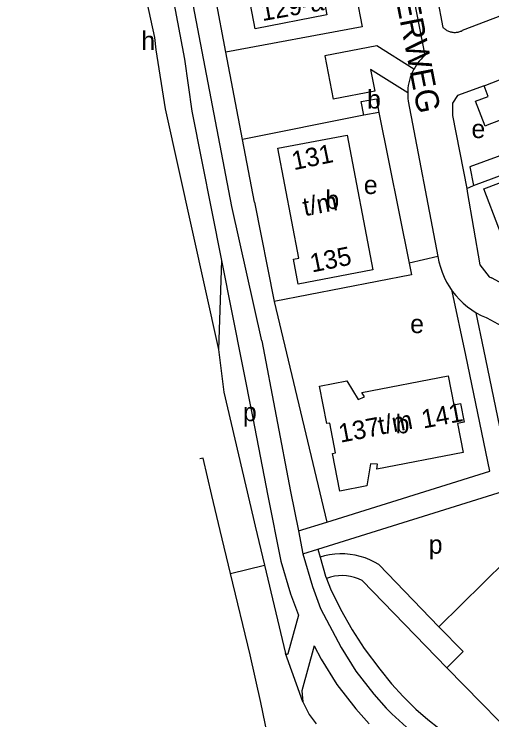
# Model space of a CAD drawing. Extents: x 159261 to 160849, y 382514 to 384534.
# Drawn here: x 159284.6 to 159387.5, y 383631.8 to 383783.7 of the extents above; entities that cross this region are included whole.
import ezdxf

# ---------------------------------------------------------------- set-up
doc = ezdxf.new("R2010")
doc.units = 0
for name, color, linetype in [('BLT_Basislijn', 7, 'Continuous'), ('BLT_Bebouwing', 7, 'Continuous'), ('BLT_Centroide', 7, 'Continuous'), ('BLT_Huisnummer_reeks', 7, 'Continuous'), ('BLT_Straatnaam', 7, 'Continuous'), ('BLT_Vlakafsluiter', 7, 'Continuous')]:
    doc.layers.add(name, color=color, linetype=linetype)

msp = doc.modelspace()

# ---------------------------------------------------------------- linework, layer by layer
at = {"layer": 'BLT_Basislijn'}
for p, q in [((159331.48, 383742.29), (159313.79, 383834.72)), ((159363.49, 383824.34), (159372.99, 383774.82)), ((159330.21, 383775.53), (159323.42, 383811.02)), ((159372.94, 383801.64), (159376.92, 383780.88)), ((159357.47, 383791.8), (159359.52, 383781.02)), ((159359.52, 383781.02), (159330.21, 383775.53)), ((159333.81, 383756.74), (159330.21, 383775.53)), ((159362.71, 383776.89), (159351.53, 383774.75)), ((159370.65, 383771.88), (159362.71, 383776.89)), ((159351.53, 383774.75), (159353.31, 383765.45)), ((159361.34, 383771.84), (159362.27, 383767.17)), ((159369.33, 383766.81), (159361.34, 383771.84)), ((159362.27, 383767.17), (159353.31, 383765.45)), ((159369.45, 383765), (159375.85, 383731.55)), ((159359.9, 383761.96), (159333.81, 383756.74)), ((159363.15, 383762.56), (159369.66, 383730.13)), ((159336.39, 383743.23), (159333.81, 383756.74)), ((159382.03, 383746.18), (159383.52, 383746.85)), ((159337.91, 383713.36), (159331.48, 383742.29)), ((159336.39, 383743.23), (159340.62, 383721.83)), ((159375.85, 383731.55), (159369.66, 383730.13)), ((159340.62, 383721.83), (159351.9, 383674.35)), ((159386.34, 383718.35), (159393.73, 383714.24)), ((159349.98, 383668.51), (159405.99, 383686.02)), ((159351.9, 383674.35), (159386.99, 383685.32)), ((159345.82, 383672.45), (159351.9, 383674.35)), ((159346.8, 383667.51), (159349.98, 383668.51)), ((159376.05, 383651.84), (159363.13, 383665.21)), ((159377.74, 383643), (159359.51, 383661.77))]:
    msp.add_line(p, q, dxfattribs=at)
for points in [[(159284.62, 383935.86), (159290.4, 383905.35), (159296.75, 383872.44), (159307.34, 383816.38), (159311.89, 383792.28), (159314.82, 383778.68), (159315.15, 383776.07), (159317.1, 383763.37)], [(159301.4, 383876.04), (159302.79, 383871.79), (159313.75, 383813.92), (159321.28, 383774.05), (159322.88, 383762.86)], [(159454.25, 383808.11), (159381.04, 383780.17)], [(159376.92, 383780.88), (159377.04, 383780.76), (159377.18, 383780.64), (159377.32, 383780.53), (159377.47, 383780.42), (159377.62, 383780.32), (159377.79, 383780.23), (159377.95, 383780.15), (159378.13, 383780.07), (159378.31, 383780), (159378.49, 383779.94), (159378.68, 383779.9), (159378.87, 383779.86), (159379.06, 383779.83), (159379.25, 383779.81), (159379.44, 383779.81), (159379.63, 383779.81), (159379.82, 383779.82), (159380.01, 383779.85), (159380.19, 383779.88), (159380.37, 383779.92), (159380.55, 383779.97), (159380.72, 383780.03), (159380.88, 383780.09), (159381.04, 383780.17)], [(159372.99, 383774.82), (159372.59, 383774.44), (159372.2, 383774.04), (159371.83, 383773.61), (159371.48, 383773.16), (159371.15, 383772.69), (159370.85, 383772.2), (159370.65, 383771.88)], [(159370.65, 383771.88), (159370.31, 383771.17), (159370.08, 383770.63), (159369.88, 383770.08), (159369.71, 383769.52), (159369.58, 383768.95), (159369.47, 383768.38), (159369.39, 383767.81), (159369.33, 383766.81)], [(159385.78, 383768.32), (159380.04, 383766.22), (159378.99, 383764.56), (159378.99, 383761.92), (159382.03, 383746.18)], [(159369.33, 383766.81), (159369.33, 383766.67), (159369.34, 383766.1), (159369.38, 383765.54), (159369.45, 383765)], [(159322.88, 383762.86), (159329.28, 383730.65)], [(159471.33, 383761.42), (159472.91, 383757.63), (159473.56, 383755.8), (159473.43, 383754.63), (159473.3, 383753.71), (159471.87, 383752.85), (159394.05, 383723.68), (159392.55, 383724.18), (159387.36, 383726.93)], [(159382.03, 383746.18), (159382.16, 383745.51), (159384.88, 383729.76), (159386.87, 383727.18), (159387.36, 383726.93)], [(159375.85, 383731.55), (159376.07, 383730.4), (159376.37, 383729.27), (159376.74, 383728.17), (159377.19, 383727.09), (159377.71, 383726.04), (159378.3, 383725.03), (159378.88, 383724.05)], [(159329.28, 383730.65), (159328.61, 383711.55)], [(159329.28, 383730.65), (159336.02, 383696.7), (159339.22, 383680), (159342.02, 383665.93), (159344.13, 383658.9), (159345.8, 383654.3)], [(159369.66, 383730.13), (159370.17, 383727.58), (159340.62, 383721.83)], [(159378.88, 383724.05), (159379.69, 383723.15), (159380.47, 383722.29), (159381.31, 383721.48), (159382.21, 383720.73), (159383.15, 383720.04), (159384.06, 383719.4)], [(159386.99, 383685.32), (159381.83, 383710.27), (159378.88, 383724.05)], [(159390.91, 383686.55), (159385.74, 383711.53), (159384.06, 383719.4)], [(159384.06, 383719.4), (159385.17, 383718.86), (159386.24, 383718.38), (159386.34, 383718.35)], [(159337.91, 383713.36), (159344.13, 383680.96), (159345.82, 383672.45)], [(159328.61, 383711.55), (159329.73, 383702.33), (159336.04, 383675.32)], [(159331.18, 383663.3), (159328.98, 383672.54), (159327.18, 383680.05), (159325.33, 383688.12), (159324.61, 383687.96)], [(159336.04, 383675.32), (159336.51, 383673.46), (159338.54, 383665.09)], [(159345.82, 383672.45), (159346.8, 383667.51)], [(159349.98, 383668.51), (159350.47, 383666.8)], [(159346.8, 383667.51), (159348.87, 383660.47), (159350.59, 383655.77)], [(159363.13, 383665.21), (159362.18, 383665.76), (159361.18, 383666.24), (159360.16, 383666.65), (159359.1, 383666.98), (159358.03, 383667.23), (159356.94, 383667.4), (159355.84, 383667.5), (159354.74, 383667.51), (159353.63, 383667.45), (159352.54, 383667.3), (159351.46, 383667.08), (159350.47, 383666.8)], [(159350.47, 383666.8), (159351.62, 383662.72), (159351.83, 383662.22)], [(159338.54, 383665.09), (159343.03, 383646.03)], [(159337.17, 383620.51), (159337.66, 383620.55), (159339.48, 383620.64), (159339.77, 383620.64), (159340, 383620.72), (159340.23, 383620.87), (159340.41, 383621.11), (159340.54, 383621.47), (159340.49, 383621.94), (159337.73, 383635.51), (159335.41, 383645.78), (159331.18, 383663.3)], [(159359.51, 383661.77), (159358.72, 383662.13), (159357.9, 383662.42), (159357.05, 383662.64), (159356.19, 383662.77), (159355.32, 383662.83), (159354.45, 383662.8), (159353.59, 383662.7), (159352.74, 383662.51), (159351.83, 383662.22)], [(159351.83, 383662.22), (159352.73, 383660.02), (159354.89, 383655.62), (159357.39, 383651.19), (159360, 383647.14), (159363.37, 383642.71), (159365.87, 383639.52), (159368.35, 383636.77), (159371.06, 383634.06), (159373.7, 383631.88), (159376.07, 383630), (159378.58, 383627.91), (159380.71, 383625.99), (159382.83, 383624.07), (159385.62, 383621.28), (159389, 383617.58), (159391.09, 383615), (159393.29, 383611.81), (159394.9, 383609.44), (159396.12, 383607.31)], [(159350.59, 383655.77), (159355.02, 383647.32), (159358.16, 383642.23), (159362.02, 383637.34), (159364.73, 383634.31), (159365.93, 383633.07), (159369.84, 383629.45)], [(159345.8, 383654.3), (159343.53, 383646.02), (159343.45, 383645.88), (159343.3, 383645.83), (159343.15, 383645.88), (159343.03, 383646.03)], [(159349.18, 383647.7), (159346.54, 383638.05), (159346.76, 383635.67)], [(159349.18, 383647.7), (159350.68, 383644.84), (159354.06, 383639.36), (159358.19, 383634.12), (159361.07, 383630.91)], [(159346.76, 383635.67), (159348.15, 383632.92), (159349.6, 383630.9)]]:
    msp.add_lwpolyline(points, dxfattribs=at)
at = {"layer": 'BLT_Bebouwing'}
for p, q in [((159385.78, 383768.32), (159391.61, 383770.56)), ((159363.15, 383762.56), (159359.9, 383761.96))]:
    msp.add_line(p, q, dxfattribs=at)
for points in [[(159346.4, 383812.62), (159351.96, 383783.55), (159336.47, 383780.58), (159334.39, 383791.46), (159333.27, 383791.24), (159332.3, 383796.29), (159330.45, 383795.93), (159329.57, 383800.55), (159331.34, 383800.89), (159329.54, 383810.27), (159336.77, 383811.65), (159336.93, 383810.8), (159346.4, 383812.62)], [(159391.88, 383761.88), (159386.43, 383759.79), (159385.98, 383759.6), (159383.93, 383764.96), (159386.66, 383766.01), (159385.78, 383768.32)], [(159359.9, 383761.96), (159359.34, 383764.92), (159362.6, 383765.52), (159363.15, 383762.56)], [(159391.88, 383761.88), (159394.45, 383755.13), (159382.7, 383750.83), (159383.52, 383746.85)], [(159356.29, 383757.7), (159361.85, 383728.67), (159345.76, 383725.59), (159344.73, 383730.98), (159345.93, 383731.21), (159341.4, 383754.85), (159356.29, 383757.7)], [(159383.52, 383746.85), (159398.77, 383752.49)], [(159392.19, 383729.18), (159385.71, 383746.11), (159391.59, 383748.36), (159398.08, 383731.44)], [(159378.07, 383705.86), (159379.3, 383699.59), (159380.72, 383699.86), (159381.49, 383695.9), (159380.06, 383695.6), (159381.25, 383689.34), (159362.68, 383685.75), (159362.87, 383686.8), (159361.36, 383686.88), (159360.57, 383682.2), (159354.7, 383681.05), (159353.14, 383689.13), (159353.81, 383689.27), (159352.59, 383695.67), (159351.9, 383695.55), (159350.34, 383703.63), (159356.21, 383704.77), (159358.67, 383700.78), (159360.05, 383701.35), (159359.49, 383702.25), (159378.07, 383705.86)], [(159376.05, 383651.84), (159400.05, 383675.46), (159401.93, 383665.21)], [(159377.74, 383643), (159381.27, 383646.48), (159376.05, 383651.84)], [(159414.91, 383604.83), (159414.91, 383605.09), (159377.74, 383643)]]:
    msp.add_lwpolyline(points, dxfattribs=at)
at = {"layer": 'BLT_Vlakafsluiter'}
for p, q in [((159317.1, 383763.37), (159328.61, 383711.55)), ((159331.18, 383663.3), (159338.54, 383665.09)), ((159346.76, 383635.67), (159343.03, 383646.03))]:
    msp.add_line(p, q, dxfattribs=at)

# ---------------------------------------------------------------- texts
at = {"layer": 'BLT_Centroide'}
for s, p in [('h', (159312, 383776)), ('b', (159360.59, 383763.4)), ('e', (159383.06, 383757.04)), ('e', (159359.89, 383744.99)), ('b', (159351.62, 383741.77)), ('e', (159369.87, 383715.05)), ('p', (159333.87, 383696.08)), ('b', (159366.74, 383693.47)), ('p', (159373.86, 383667.55))]:
    msp.add_text(s, height=4, dxfattribs=at).set_placement(p)
at = {"layer": 'BLT_Huisnummer_reeks'}
for s, rotation, p in [('129-a', 10.2392, (159338.05, 383782.21)), ('131', 11.676, (159344.83, 383750.11)), ('t/m', 10.673, (159347.16, 383740.21)), ('135', 11.4138, (159348.74, 383728.08)), ('141', 10.697, (159372.7, 383694.49)), ('137', 10.697, (159354.86, 383691.44)), ('t/m', 10.697, (159363.35, 383693.15))]:
    msp.add_text(s, height=4, rotation=rotation, dxfattribs=at).set_placement(p)
at = {"layer": 'BLT_Straatnaam'}
msp.add_text('LANGENAKKERWEG', height=5, rotation=280.9843, dxfattribs=at).set_placement((159358.97, 383826.96))

doc.saveas('drawing.dxf')
